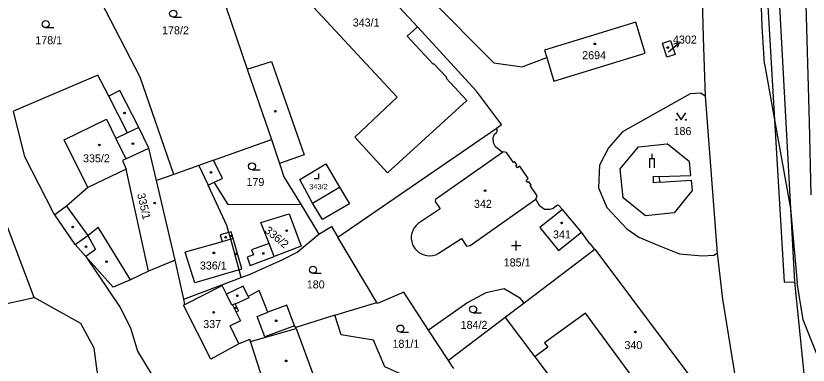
# Model space of a CAD drawing. Extents: x -679220 to -673243, y -1075091 to -1066557.
# Drawn here: x -676729.1 to -676560.9, y -1071182.6 to -1071108.5 of the extents above; entities that cross this region are included whole.
import ezdxf

# ---------------------------------------------------------------- set-up
doc = ezdxf.new("R2010")
doc.units = 0
for name, color, linetype in [('Hranice parcel', 7, 'Continuous'), ('Parcelní čísla', 7, 'Continuous'), ('Pop  PČ popisy', 7, 'Continuous'), ('Vnitřní kresba', 7, 'Continuous'), ('Značky budov', 7, 'Continuous'), ('Značky kultur', 7, 'Continuous')]:
    doc.layers.add(name, color=color, linetype=linetype)

msp = doc.modelspace()

# ---------------------------------------------------------------- linework, layer by layer
at = {"layer": 'Hranice parcel'}
for p, q in [((-676582.77, -1071125.51), (-676580.24, -1071158.83)), ((-676660.76, -1071155.46), (-676627.17, -1071132.37)), ((-676687.17, -1071139.12), (-676674.87, -1071134.72)), ((-676695.59, -1071142.14), (-676699.28, -1071143.46)), ((-676695.3, -1071160.38), (-676699.28, -1071143.46)), ((-676668.55, -1071148.59), (-676664.77, -1071154.86)), ((-676609.07, -1071154.39), (-676613.06, -1071149.56)), ((-676652.47, -1071169.32), (-676660.76, -1071155.46)), ((-676606.25, -1071158.07), (-676621.23, -1071169.45)), ((-676693.47, -1071168.62), (-676695.3, -1071160.38)), ((-676685.37, -1071165.57), (-676681.27, -1071164.03)), ((-676693.47, -1071168.62), (-676685.37, -1071165.57)), ((-676661.37, -1071172.06), (-676652.47, -1071169.32)), ((-676621.23, -1071169.45), (-676625.26, -1071172.51)), ((-676661.37, -1071172.06), (-676669.69, -1071174.62)), ((-676625.26, -1071172.51), (-676637.29, -1071181.65)), ((-676637.29, -1071181.65), (-676641.5, -1071175.18)), ((-676674.54, -1071192.22), (-676679.33, -1071177.62))]:
    msp.add_line(p, q, dxfattribs=at)
for points in [[(-676566.43, -1070961.91), (-676569.23, -1071023.51), (-676569.31, -1071051.96), (-676567.07, -1071105.14), (-676564.66, -1071149.4), (-676563.82, -1071164.93), (-676560.23, -1071200.41)], [(-676560.3, -1071146.5), (-676560.63, -1071131.04), (-676561.44, -1071103.53), (-676561.64, -1071096.36), (-676561.94, -1071087.67), (-676561.7, -1071087.65), (-676561.93, -1071081.5), (-676562.1, -1071081.5), (-676562.67, -1071060.48), (-676562.54, -1071060.48), (-676562.52, -1071055.56), (-676562.05, -1071055.53), (-676562.5, -1071049.32), (-676562.68, -1071049.33), (-676563.11, -1071042.56), (-676562.77, -1071037.79), (-676568.16, -1071037.22), (-676567.55, -1071023.82)], [(-676725.22, -1071168.28), (-676731.67, -1071151.24), (-676735.33, -1071145.49), (-676736.53, -1071139.93), (-676737.25, -1071134.45), (-676745.58, -1071118.19), (-676749.48, -1071113.45), (-676756.02, -1071105.93), (-676761.71, -1071102.77), (-676769.7, -1071100.12), (-676774.51, -1071095.47), (-676778.42, -1071091.75), (-676780.54, -1071085.7), (-676783.44, -1071075.78), (-676787.2, -1071065.69), (-676789.62, -1071058.9), (-676793.14, -1071053.68)], [(-676627.17, -1071132.37), (-676626.01, -1071131.56), (-676631.34, -1071124.45), (-676643.88, -1071110.8), (-676655.44, -1071098.3), (-676668.66, -1071084.17), (-676671.17, -1071081.43), (-676682.22, -1071069.66), (-676683.61, -1071068.17)], [(-676695.59, -1071142.14), (-676702.73, -1071121.52), (-676717.26, -1071093.23)], [(-676583.71, -1071095.79), (-676583.67, -1071096.7), (-676583.25, -1071113.06), (-676582.77, -1071125.51)], [(-676686.34, -1071101.66), (-676685.72, -1071102.87), (-676680.04, -1071119.82), (-676674.87, -1071134.72)], [(-676616.91, -1071115.79), (-676616.43, -1071117.35), (-676614.9, -1071122.36), (-676595.5, -1071116.41), (-676597.51, -1071109.84), (-676616.91, -1071115.79)], [(-676590.13, -1071113.72), (-676589.2, -1071116.66), (-676590.96, -1071117.23), (-676591.85, -1071114.28), (-676590.13, -1071113.72)], [(-676703, -1071132.17), (-676707.03, -1071124.33), (-676709.4, -1071125.55), (-676711.73, -1071121.04), (-676729.63, -1071128.68)], [(-676582.77, -1071125.51), (-676583.7, -1071124.9), (-676585.99, -1071125.06), (-676600.34, -1071133.1), (-676603.31, -1071136.48), (-676605.24, -1071140.15), (-676605.42, -1071144.96), (-676603.64, -1071149.19), (-676599.43, -1071153.7), (-676596.85, -1071155.5), (-676592.46, -1071157.31), (-676588.23, -1071159.03), (-676583.41, -1071159.44), (-676580.97, -1071159.31), (-676580.24, -1071158.83)], [(-676720.82, -1071150.7), (-676721.11, -1071150.27), (-676727.17, -1071138.38), (-676729.63, -1071128.68)], [(-676703, -1071132.17), (-676705.38, -1071133.34), (-676707.85, -1071134.55), (-676705.76, -1071138.82), (-676706.5, -1071139.16), (-676705.72, -1071141.02), (-676713.86, -1071144.92), (-676718.37, -1071148.92), (-676720.82, -1071150.7)], [(-676699.28, -1071143.46), (-676700.89, -1071136.56), (-676703, -1071132.17)], [(-676625.8, -1071137.46), (-676627.27, -1071136.32), (-676627.73, -1071135.47), (-676627.81, -1071134.38), (-676627.52, -1071133.63), (-676627.08, -1071133.26), (-676626.9, -1071132.84), (-676627.17, -1071132.37)], [(-676674.87, -1071134.72), (-676673.18, -1071139.84), (-676672.25, -1071142.63), (-676668.55, -1071148.59)], [(-676625.8, -1071137.46), (-676640.02, -1071147.48), (-676640.1, -1071147.88), (-676639.04, -1071149.48), (-676643.72, -1071152.55)], [(-676618.77, -1071147.37), (-676618.45, -1071146.7), (-676619.96, -1071144.53), (-676619.7, -1071144.35), (-676620.2, -1071143.69), (-676620.46, -1071143.89), (-676620.82, -1071143.41), (-676620.34, -1071143.04), (-676622.17, -1071140.42), (-676622.66, -1071140.77), (-676623.02, -1071140.28), (-676622.75, -1071140.09), (-676623.24, -1071139.42), (-676623.51, -1071139.6), (-676624.97, -1071137.48), (-676625.65, -1071137.36), (-676625.8, -1071137.46)], [(-676687.17, -1071139.12), (-676690.27, -1071140.23), (-676695.59, -1071142.14)], [(-676686.98, -1071143.81), (-676685.27, -1071143.02), (-676687.17, -1071139.12)], [(-676660.44, -1071144.88), (-676658.3, -1071148.36), (-676664.04, -1071151.74), (-676666.12, -1071148.22), (-676668.86, -1071143.2), (-676663.29, -1071139.91), (-676660.44, -1071144.88)], [(-676681.27, -1071164.03), (-676681.73, -1071162.37), (-676683.5, -1071155.91), (-676683.9, -1071154.46), (-676684.31, -1071153.02), (-676688.31, -1071144.43), (-676686.98, -1071143.81)], [(-676668.55, -1071148.59), (-676684.07, -1071148.53), (-676686.98, -1071143.81)], [(-676639.44, -1071158.96), (-676634.5, -1071155.78), (-676633.44, -1071157.35), (-676632.71, -1071157.24), (-676618.77, -1071147.37)], [(-676613.06, -1071149.56), (-676613.83, -1071148.77), (-676614.17, -1071148.7), (-676614.38, -1071148.81), (-676614.76, -1071149.14), (-676615.08, -1071149.38), (-676615.8, -1071149.6), (-676616.87, -1071149.56), (-676617.91, -1071148.9), (-676618.77, -1071147.37)], [(-676613.06, -1071149.56), (-676617.86, -1071153.44), (-676613.94, -1071158.32), (-676609.07, -1071154.39)], [(-676714.26, -1071159.56), (-676716.51, -1071157.02), (-676720.82, -1071150.7)], [(-676643.72, -1071152.55), (-676644.17, -1071152.97), (-676644.55, -1071153.45), (-676644.59, -1071153.5), (-676644.88, -1071154.05), (-676645.07, -1071154.63), (-676645.17, -1071155.24), (-676645.17, -1071155.85), (-676645.08, -1071156.46), (-676644.89, -1071157.04), (-676644.75, -1071157.33), (-676644.43, -1071157.85), (-676644.02, -1071158.31), (-676643.54, -1071158.7), (-676643.01, -1071159.01), (-676642.44, -1071159.25), (-676641.84, -1071159.39), (-676641.82, -1071159.39), (-676641.21, -1071159.43), (-676640.6, -1071159.37), (-676640, -1071159.21), (-676639.44, -1071158.96)], [(-676664.77, -1071154.86), (-676662.13, -1071153.17), (-676660.76, -1071155.46)], [(-676606.25, -1071158.07), (-676607.11, -1071156.88), (-676607.19, -1071156.94), (-676609.07, -1071154.39)], [(-676681.27, -1071164.03), (-676679.38, -1071163.32), (-676672.42, -1071160.21), (-676669.42, -1071158.67), (-676664.77, -1071154.86)], [(-676582.77, -1071189.23), (-676606.14, -1071157.99), (-676606.25, -1071158.07)], [(-676695.3, -1071160.38), (-676700.96, -1071162.68), (-676704.74, -1071164.5), (-676708.46, -1071166.11), (-676714.26, -1071159.56)], [(-676714.26, -1071159.56), (-676706.99, -1071170.4), (-676704.8, -1071174.72), (-676703.28, -1071179.64), (-676700.03, -1071185.04), (-676698.82, -1071191.33), (-676701.52, -1071203.91), (-676703.72, -1071213.25), (-676705.55, -1071217.25)], [(-676580.24, -1071158.83), (-676579.09, -1071168.64), (-676576.19, -1071186.56), (-676571.69, -1071204.25)], [(-676669.69, -1071174.62), (-676669.94, -1071174.28), (-676671.61, -1071169.9), (-676675.61, -1071171.42), (-676677.44, -1071166.8), (-676679.83, -1071168.03), (-676680.89, -1071165.85), (-676684.4, -1071167.56), (-676685.28, -1071165.75), (-676685.37, -1071165.57)], [(-676641.5, -1071175.18), (-676646.76, -1071167.15), (-676652.32, -1071169.57), (-676652.47, -1071169.32)], [(-676621.23, -1071169.45), (-676621.97, -1071168.49), (-676625.43, -1071166.45), (-676629.36, -1071167.29), (-676633.16, -1071169.37), (-676641.5, -1071175.18)], [(-676766.17, -1071173.98), (-676758.83, -1071175.12), (-676758.81, -1071175.27), (-676754.44, -1071174.78), (-676754.47, -1071174.63), (-676748.42, -1071173.39), (-676725.22, -1071168.28)], [(-676709.37, -1071194.33), (-676710.67, -1071190.16), (-676711.86, -1071183.83), (-676712.45, -1071179.03), (-676715.29, -1071173.8), (-676725.22, -1071168.28)], [(-676679.33, -1071177.62), (-676679.46, -1071177.19), (-676681.79, -1071178.12), (-676687.72, -1071181.36), (-676693.49, -1071169.87), (-676693.22, -1071169.74), (-676693.47, -1071168.62)], [(-676669.96, -1071200.75), (-676669.2, -1071200.31), (-676661.84, -1071193.82), (-676649.68, -1071187.97), (-676647.3, -1071184.53), (-676650.76, -1071183.01), (-676653.23, -1071177.35), (-676660.03, -1071176.21), (-676661.37, -1071172.06)], [(-676625.26, -1071172.51), (-676618.98, -1071180.87), (-676612.73, -1071189.14), (-676613.95, -1071190.03), (-676611.7, -1071193.1), (-676609.74, -1071195.78), (-676603.13, -1071204.8), (-676582.77, -1071189.23)], [(-676679.33, -1071177.62), (-676669.59, -1071174.88), (-676669.69, -1071174.62)], [(-676636.13, -1071183.38), (-676636.66, -1071182.62), (-676637.29, -1071181.65)]]:
    msp.add_lwpolyline(points, dxfattribs=at)
at = {"layer": 'Pop  PČ popisy'}
for p, q in [((-676590.6, -1071116.15), (-676588.34, -1071114.18)), ((-676588.34, -1071114.18), (-676589.42, -1071114.46)), ((-676588.34, -1071114.18), (-676588.76, -1071115.22))]:
    msp.add_line(p, q, dxfattribs=at)
at = {"layer": 'Vnitřní kresba'}
for p, q in [((-676671.02, -1071074.78), (-676627.66, -1071118.45)), ((-676570.68, -1071110.75), (-676571.15, -1071096.54)), ((-676670.78, -1071101.37), (-676648.14, -1071125.74)), ((-676569.57, -1071105.21), (-676568.06, -1071130.57)), ((-676643.88, -1071110.8), (-676646.02, -1071112.82)), ((-676570.21, -1071118.7), (-676570.68, -1071110.75)), ((-676646.02, -1071112.82), (-676640.55, -1071118.71)), ((-676621.66, -1071119.28), (-676616.43, -1071117.35)), ((-676680.04, -1071119.82), (-676674.83, -1071118.17)), ((-676674.83, -1071118.17), (-676667.91, -1071137.96)), ((-676640.55, -1071118.71), (-676640.44, -1071118.61)), ((-676640.44, -1071118.61), (-676637.64, -1071121.58)), ((-676627.66, -1071118.45), (-676621.66, -1071119.28)), ((-676570.21, -1071118.7), (-676568.06, -1071130.57)), ((-676637.64, -1071121.58), (-676637.78, -1071121.69)), ((-676637.78, -1071121.69), (-676633.36, -1071126.46)), ((-676705.38, -1071133.34), (-676709.4, -1071125.55)), ((-676648.14, -1071125.74), (-676657.16, -1071134.26)), ((-676650.21, -1071141.81), (-676633.36, -1071126.46)), ((-676718.82, -1071134.81), (-676709.88, -1071130.42)), ((-676709.88, -1071130.42), (-676707.85, -1071134.55)), ((-676568.06, -1071130.57), (-676566.02, -1071164.99)), ((-676568.06, -1071130.57), (-676564.66, -1071149.4)), ((-676657.16, -1071134.26), (-676650.21, -1071141.81)), ((-676713.86, -1071144.92), (-676718.82, -1071134.81)), ((-676596.98, -1071136.27), (-676590.89, -1071135.63)), ((-676586.14, -1071139.48), (-676590.89, -1071135.63)), ((-676705.76, -1071138.82), (-676700.89, -1071136.56)), ((-676600.87, -1071140.94), (-676596.98, -1071136.27)), ((-676667.91, -1071137.96), (-676673.18, -1071139.84)), ((-676585.87, -1071142.38), (-676586.14, -1071139.48)), ((-676700.96, -1071162.68), (-676705.72, -1071141.02)), ((-676690.27, -1071140.23), (-676688.31, -1071144.43)), ((-676600.17, -1071147.1), (-676600.87, -1071140.94)), ((-676593.78, -1071142.53), (-676592.6, -1071142.57)), ((-676593.75, -1071143.95), (-676593.78, -1071142.53)), ((-676592.6, -1071142.57), (-676585.87, -1071142.38)), ((-676592.6, -1071142.57), (-676592.44, -1071143.81)), ((-676592.44, -1071143.81), (-676593.75, -1071143.95)), ((-676592.44, -1071143.81), (-676585.77, -1071143.39)), ((-676585.77, -1071143.39), (-676585.57, -1071145.54)), ((-676666.12, -1071148.22), (-676660.44, -1071144.88)), ((-676585.57, -1071145.54), (-676589.38, -1071150.3)), ((-676595.47, -1071150.97), (-676600.17, -1071147.1)), ((-676718.37, -1071148.92), (-676713.86, -1071155.12)), ((-676564.66, -1071149.4), (-676563.28, -1071165.17)), ((-676677.08, -1071152.32), (-676671.1, -1071150.52)), ((-676671.1, -1071150.52), (-676668.55, -1071157.36)), ((-676589.38, -1071150.3), (-676595.47, -1071150.97)), ((-676675.36, -1071156.8), (-676677.08, -1071152.32)), ((-676713.86, -1071155.12), (-676711.6, -1071153.31)), ((-676704.74, -1071164.5), (-676711.6, -1071153.31)), ((-676683.9, -1071154.46), (-676685.74, -1071154.97)), ((-676683.42, -1071154.33), (-676683.9, -1071154.46)), ((-676683, -1071155.77), (-676683.42, -1071154.33)), ((-676716.51, -1071157.02), (-676713.86, -1071155.12)), ((-676713.86, -1071155.12), (-676712.22, -1071158.09)), ((-676685.74, -1071154.97), (-676685.33, -1071156.43)), ((-676683.5, -1071155.91), (-676685.33, -1071156.43)), ((-676683, -1071155.77), (-676683.5, -1071155.91)), ((-676681.11, -1071162.19), (-676683, -1071155.77)), ((-676685.33, -1071156.43), (-676693.19, -1071158.66)), ((-676675.36, -1071156.8), (-676679.06, -1071158.19)), ((-676674.3, -1071159.57), (-676675.36, -1071156.8)), ((-676668.55, -1071157.36), (-676674.3, -1071159.57)), ((-676712.22, -1071158.09), (-676714.26, -1071159.56)), ((-676691.12, -1071165.14), (-676693.19, -1071158.66)), ((-676678.67, -1071159.21), (-676680.02, -1071159.74)), ((-676679.34, -1071161.51), (-676674.3, -1071159.57)), ((-676679.06, -1071158.19), (-676678.67, -1071159.21)), ((-676680.02, -1071159.74), (-676679.34, -1071161.51)), ((-676681.73, -1071162.37), (-676691.12, -1071165.14)), ((-676681.73, -1071162.37), (-676681.11, -1071162.19)), ((-676693.22, -1071169.74), (-676685.28, -1071165.75)), ((-676566.02, -1071164.99), (-676563.82, -1071164.93)), ((-676562.01, -1071173.01), (-676563.28, -1071165.17)), ((-676683.25, -1071169.93), (-676684.4, -1071167.56)), ((-676679.83, -1071168.03), (-676679.69, -1071168.32)), ((-676682.59, -1071169.6), (-676683.1, -1071169.86)), ((-676682.54, -1071169.71), (-676682.59, -1071169.6)), ((-676679.69, -1071168.32), (-676682.54, -1071169.71)), ((-676682.54, -1071169.71), (-676681.85, -1071171.12)), ((-676683.1, -1071169.86), (-676683.25, -1071169.93)), ((-676683.1, -1071169.86), (-676682.36, -1071171.37)), ((-676681.85, -1071171.12), (-676682.36, -1071171.37)), ((-676682.36, -1071171.37), (-676681.44, -1071173.25)), ((-676677.91, -1071172.29), (-676675.61, -1071171.42)), ((-676676.24, -1071176.66), (-676677.91, -1071172.29)), ((-676608.23, -1071171.61), (-676616.89, -1071177.89)), ((-676597.15, -1071186.62), (-676608.23, -1071171.61)), ((-676559.18, -1071180.11), (-676562.01, -1071173.01)), ((-676681.44, -1071173.25), (-676683.65, -1071174.32)), ((-676681.79, -1071178.12), (-676683.65, -1071174.32)), ((-676669.94, -1071174.28), (-676676.24, -1071176.66)), ((-676669.59, -1071174.88), (-676665.88, -1071185.03)), ((-676616.89, -1071177.89), (-676616.19, -1071178.85)), ((-676616.19, -1071178.85), (-676618.98, -1071180.87))]:
    msp.add_line(p, q, dxfattribs=at)
at = {"layer": 'Značky budov'}
for centre in [(-676606.22, -1071114.43), (-676590.73, -1071115.21), (-676706.04, -1071129.11), (-676674.04, -1071128.72), (-676711.4, -1071135.89), (-676704.27, -1071135.6), (-676687.68, -1071141.72), (-676629.51, -1071145.6), (-676699.64, -1071148.22), (-676613.27, -1071152.43), (-676717.06, -1071153.3), (-676671.64, -1071154.08), (-676684.56, -1071155.47), (-676683.43, -1071155.22), (-676714.23, -1071157.51), (-676687.07, -1071158.8), (-676682.37, -1071159.01), (-676676.59, -1071158.93), (-676709.85, -1071160.68), (-676682.08, -1071167.91), (-676687.13, -1071171.41), (-676682.47, -1071170.5), (-676673.84, -1071173.22), (-676597.62, -1071175.57), (-676671.73, -1071181.73)]:
    msp.add_circle(centre, 0.175, dxfattribs=at)
at = {"layer": 'Značky kultur'}
for p, q in [((-676695.71, -1071108.75), (-676693.96, -1071108.75)), ((-676722.79, -1071110.98), (-676721.04, -1071110.98)), ((-676594.06, -1071138.78), (-676594.06, -1071137.78)), ((-676594.56, -1071138.78), (-676593.56, -1071138.78)), ((-676594.56, -1071140.78), (-676594.56, -1071138.78)), ((-676593.56, -1071140.78), (-676593.56, -1071138.78)), ((-676678.98, -1071141.18), (-676677.23, -1071141.18)), ((-676664.8, -1071142.98), (-676664.8, -1071141.98)), ((-676665.8, -1071142.98), (-676664.8, -1071142.98)), ((-676622.91, -1071158.28), (-676622.91, -1071156.28)), ((-676621.91, -1071157.28), (-676623.91, -1071157.28)), ((-676666.02, -1071163.14), (-676664.27, -1071163.14)), ((-676632.05, -1071171.53), (-676630.3, -1071171.53)), ((-676647.49, -1071175.62), (-676645.74, -1071175.62))]:
    msp.add_line(p, q, dxfattribs=at)
msp.add_lwpolyline([(-676588.89, -1071129.04), (-676587.89, -1071130.54), (-676586.89, -1071129.04)], dxfattribs=at)
for centre, radius in [((-676695.71, -1071108), 0.75), ((-676722.79, -1071110.23), 0.75), ((-676588.89, -1071130.54), 0.1), ((-676586.89, -1071130.54), 0.1), ((-676678.98, -1071140.43), 0.75), ((-676666.02, -1071162.39), 0.75), ((-676632.05, -1071170.78), 0.75), ((-676647.49, -1071174.87), 0.75)]:
    msp.add_circle(centre, radius, dxfattribs=at)

# ---------------------------------------------------------------- texts
at = {"layer": 'Parcelní čísla'}
for s, height, p in [('343/1', 1.7, (-676657.6, -1071110.74)), ('178/2', 1.7, (-676698.07, -1071112.4)), ('178/1', 1.7, (-676724.97, -1071114.5)), ('4302', 1.7, (-676589.63, -1071114.36)), ('2694', 1.7, (-676608.9, -1071117.68)), ('186', 1.7, (-676589.51, -1071133.79)), ('335/2', 1.7, (-676714.85, -1071139.58)), ('179', 1.7, (-676680.15, -1071144.6)), ('343/2', 1.14, (-676666.85, -1071145.31)), ('342', 1.7, (-676631.87, -1071149.24)), ('341', 1.7, (-676615.1, -1071155.74)), ('336/1', 1.7, (-676690.04, -1071162.34)), ('185/1', 1.7, (-676625.55, -1071161.69)), ('180', 1.7, (-676667.35, -1071166.35)), ('337', 1.7, (-676689.33, -1071174.77)), ('184/2', 1.7, (-676634.7, -1071174.94)), ('181/1', 1.7, (-676649.16, -1071178.96)), ('340', 1.7, (-676599.93, -1071179.22))]:
    msp.add_text(s, height=height, dxfattribs=at).set_placement(p)
for s, rotation, p in [('335/1', 283, (-676703.38, -1071146.33)), ('336/2', 320, (-676676.44, -1071154.29))]:
    msp.add_text(s, height=1.7, rotation=rotation, dxfattribs=at).set_placement(p)

doc.saveas('drawing.dxf')
